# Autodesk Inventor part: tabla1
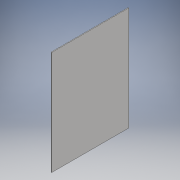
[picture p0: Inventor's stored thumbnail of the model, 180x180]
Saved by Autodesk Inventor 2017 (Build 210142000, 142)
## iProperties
Created: 2017-11
Part Number: tabla1
Material: Generic
Document SubType Name: Modeling
Designer: iusti
Density: 1 g/cm^3
Appearance: Default
Author: iusti
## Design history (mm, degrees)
sketch "Sketch1"
  geometry: L1 (599.54, 773.5)-(-550.46, 773.5); L2 (-550.46, 773.5)-(-550.46, -773.5); L3 (-550.46, -773.5)-(599.54, -773.5); L4 (599.54, -773.5)-(599.54, 773.5); L5 (599.54, 773.5)-(-550.46, -773.5); L6 (-550.46, 773.5)-(599.54, -773.5); 2 further points
  constraints: 12 end point, 2 midpoint, 2 parallel, 1 horizontal, 1 perpendicular
  dimensions: "d0" = 1547 distance of L3.end L1.start; "d2" = 1150 distance of L1.start L1.end
extrude "Extrusion1" new body sketch "Sketch1" distance "d3" = 10; taper "d4" = 0 deg
body "Solid1"
